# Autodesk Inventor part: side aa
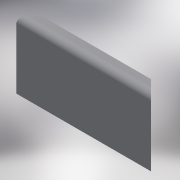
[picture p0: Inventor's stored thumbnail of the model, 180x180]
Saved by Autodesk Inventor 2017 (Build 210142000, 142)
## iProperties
Created: 2017-11
Part Number: side aa
Material: Generic
Document SubType Name: Modeling
Designer: lshopper
Density: 1 g/cm^3
Appearance: Default
Author: lshopper
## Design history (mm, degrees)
sketch "Sketch1"
  geometry: L1 (101.6, 16.803)-(-101.6, 16.803); L2 (-101.6, 16.803)-(-82.55, -2.247); L3 (-82.55, -2.247)-(82.55, -2.247); L4 (82.55, -2.247)-(101.6, 16.803); 2 further points
  constraints: 8 end point, 1 horizontal, 1 midpoint, 1 parallel, 1 vertical alignment
  dimensions: "d0" = 19.05 distance between parallel lines of L3 L1; "d1" = 203.2 distance of L1.start L1.end; "d2" = 45 deg angle of L1 L4; "d3" = 45 deg angle of L1 L2
extrude "Extrusion1" new body sketch "Sketch1" distance "d4" = 101.6; taper "d5" = 0 deg
fillet "Fillet1" dims "d8" = 9.525
body "Solid1"
